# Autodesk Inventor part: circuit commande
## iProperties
Created: 2011-01
Part Number: circuit commande
Document SubType Name: Modeling
Designer: eric
Density: 1 g/cm^3
Mass: 53.8077 g
Surface Area: 363.448 cm^2
Volume: 53.8077 cm^3
Author: eric
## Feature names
1. Base1
